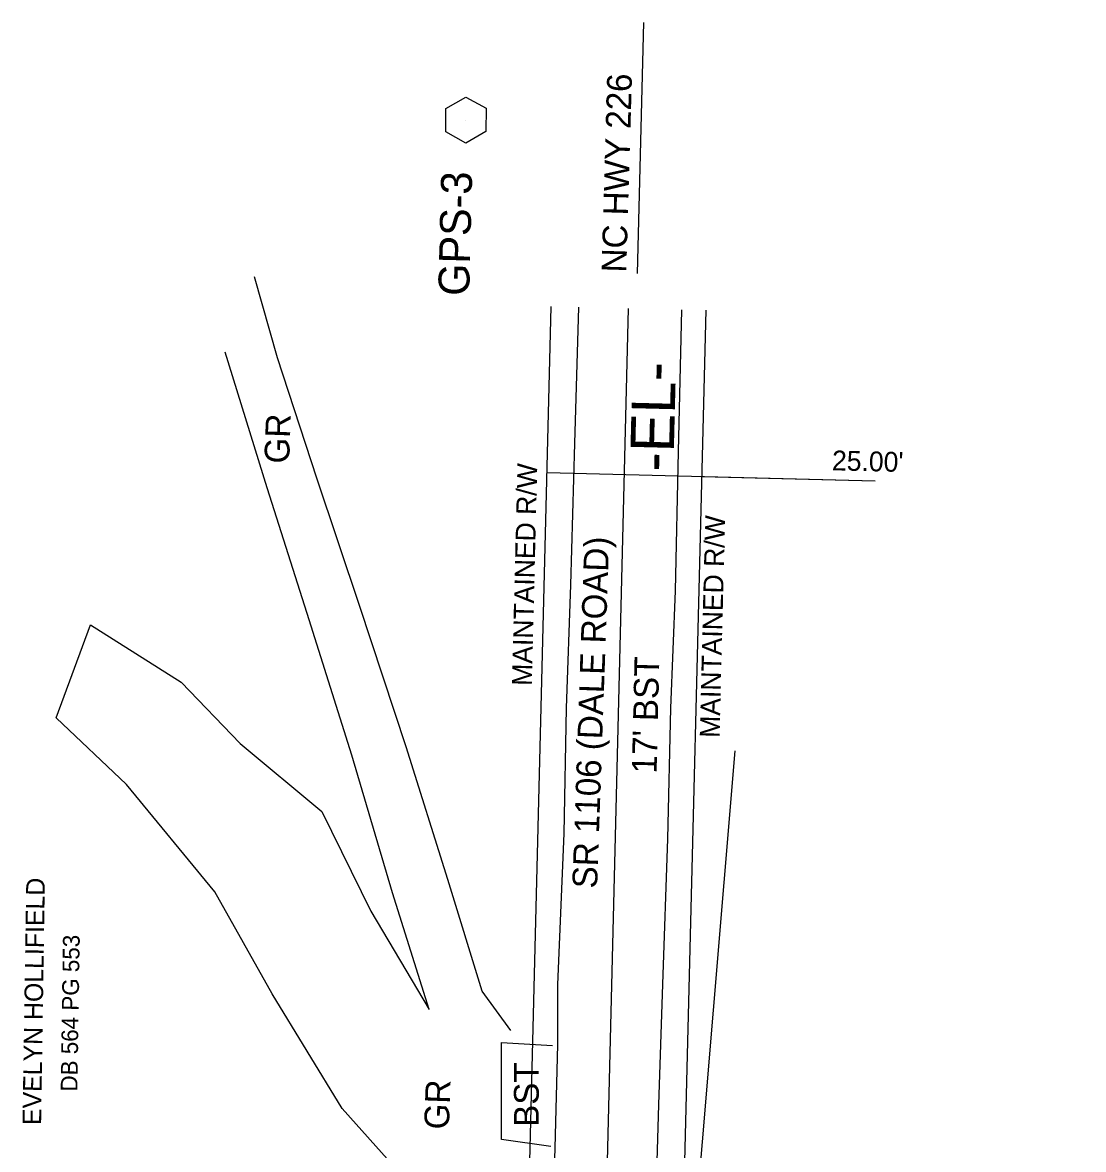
# Model space of a CAD drawing. Extents: x 1088366 to 1089341, y 781245 to 782648.
# Drawn here: x 1088767.2 to 1088938.3, y 781843.2 to 782025 of the extents above; entities that cross this region are included whole.
import ezdxf

# ---------------------------------------------------------------- set-up
doc = ezdxf.new("R2010")
doc.units = 0
for name, color, linetype in [('CTL Primary Horizontal and Vertical CELL', 7, 'Continuous'), ('CTL Primary Horizontal and Vertical Text', 7, 'Continuous'), ('Exist Horizontal Alignment', 7, 'Continuous'), ('Exist Horizontal Alignment Direction Label', 7, 'Continuous'), ('Exist Property Deed Book Text', 7, 'Continuous'), ('Exist Property Owner Text', 7, 'Continuous'), ('Exist Right of Way Line', 7, 'Continuous'), ('Exist Right of Way Line Text', 7, 'Continuous'), ('Exist Right of Way Width CELL', 7, 'Continuous'), ('Exist Roads EOP', 7, 'Continuous'), ('Exist Roads EOP Leader', 7, 'Continuous'), ('Exist Roads EOP Text', 7, 'Continuous'), ('Exist Roads Soil', 7, 'Continuous'), ('Exist Roads Soil Text', 7, 'Continuous'), ('Exist Vegetation Woods Line', 7, 'Continuous')]:
    doc.layers.add(name, color=color, linetype=linetype)

msp = doc.modelspace()

# ---------------------------------------------------------------- linework, layer by layer
at = {"layer": 'CTL Primary Horizontal and Vertical CELL'}
msp.add_line((1088838.71, 782009.27), (1088838.71, 782009.27), dxfattribs=at)
msp.add_lwpolyline([(1088835.48, 782011.14), (1088838.73, 782012.95), (1088841.98, 782011.16), (1088841.93, 782007.44), (1088838.68, 782005.55), (1088835.48, 782007.36)], close=True, dxfattribs=at)
at = {"layer": 'Exist Horizontal Alignment'}
msp.add_line((1088858.13, 781704.91), (1088864.96, 781978.89), dxfattribs=at)
at = {"layer": 'Exist Right of Way Line'}
for p, q in [((1088845.64, 781705.22), (1088852.47, 781979.2)), ((1088870.63, 781704.6), (1088877.46, 781978.58))]:
    msp.add_line(p, q, dxfattribs=at)
at = {"layer": 'Exist Right of Way Width CELL'}
for p in [(1088851.8, 781952.39), (1088876.79, 781951.76)]:
    msp.add_line(p, (1088904.72, 781951.07), dxfattribs=at)
at = {"layer": 'Exist Roads EOP'}
for points in [[(1088856.86, 781979.09), (1088856.22, 781957.08), (1088855.57, 781934.3), (1088854.88, 781914.39), (1088854.52, 781894.14), (1088853.51, 781869.82), (1088853.47, 781860.13), (1088853.06, 781843.4), (1088852.42, 781823.3), (1088852.15, 781809.3), (1088851.65, 781789.26), (1088851.14, 781767.36), (1088850.59, 781747.04), (1088849.91, 781705.29), (1088848.76, 781686.19)], [(1088873.5, 781978.67), (1088872.95, 781955.77), (1088872.48, 781933.34), (1088871.73, 781914.36), (1088871.22, 781893.29), (1088870.41, 781869.88), (1088869.8, 781850.38), (1088869.18, 781830.31), (1088868.84, 781810.65), (1088868.33, 781781.83), (1088867.86, 781767.06), (1088867.68, 781744.62), (1088867.34, 781738.14), (1088866.47, 781715.27), (1088865.39, 781693.19), (1088864.42, 781676.36)], [(1088873.5, 781978.67), (1088872.95, 781955.77), (1088872.48, 781933.34), (1088871.73, 781914.36), (1088871.22, 781893.29), (1088870.41, 781869.88), (1088869.8, 781850.38), (1088869.18, 781830.31), (1088868.84, 781810.65), (1088868.33, 781781.83), (1088867.86, 781767.06), (1088867.68, 781744.62)], [(1088852.42, 781843.65), (1088844.47, 781844.81), (1088844.47, 781860.47), (1088852.68, 781859.99)]]:
    msp.add_lwpolyline(points, dxfattribs=at)
at = {"layer": 'Exist Roads EOP Leader'}
msp.add_line((1088867.36, 782025), (1088866.35, 781984.53), dxfattribs=at)
at = {"layer": 'Exist Roads Soil'}
for points in [[(1088845.94, 781862.39), (1088841.32, 781868.72), (1088835.78, 781886.77), (1088829.08, 781908.16), (1088821.63, 781930.78), (1088814.67, 781951.51), (1088808.34, 781970.9), (1088804.6, 781983.99)], [(1088851.73, 781822.38), (1088840.35, 781825.46), (1088830.55, 781836.64), (1088818.74, 781849.8), (1088807.48, 781868.3), (1088798.2, 781884.76), (1088783.96, 781902.06), (1088772.62, 781912.82), (1088778.19, 781927.81), (1088792.77, 781918.56), (1088802.3, 781908.7), (1088815.5, 781897.74), (1088823.39, 781881.66), (1088832.79, 781865.75), (1088826.9, 781884.58), (1088820.34, 781906.83), (1088813.13, 781929.64), (1088806.68, 781949.91), (1088799.87, 781971.84)]]:
    msp.add_lwpolyline(points, dxfattribs=at)
at = {"layer": 'Exist Vegetation Woods Line'}
msp.add_lwpolyline([(1088938.32, 781707.06), (1088898.21, 781719.36), (1088881.24, 781725.94), (1088868.09, 781739.51), (1088882.14, 781907.48)], dxfattribs=at)

# ---------------------------------------------------------------- texts
at = {"layer": 'CTL Primary Horizontal and Vertical Text'}
msp.add_text('GPS-3', height=5, rotation=88.5723, dxfattribs=at).set_placement((1088839.24, 781980.86))
at = {"layer": 'Exist Horizontal Alignment Direction Label'}
msp.add_text('-EL-', height=7, rotation=88.5723, dxfattribs=at).set_placement((1088872.17, 781952.49))
at = {"layer": 'Exist Property Deed Book Text'}
msp.add_text('DB 564 PG 553', height=2.7, rotation=89.1135, dxfattribs=at).set_placement((1088776.05, 781852.52))
at = {"layer": 'Exist Property Owner Text'}
msp.add_text('EVELYN HOLLIFIELD', height=3, rotation=89.1135, dxfattribs=at).set_placement((1088770.2, 781847.11))
at = {"layer": 'Exist Right of Way Line Text'}
for p in [(1088849.34, 781917.96), (1088879.63, 781909.57)]:
    msp.add_text('MAINTAINED R/W', height=3.2, rotation=88.5723, dxfattribs=at).set_placement(p)
at = {"layer": 'Exist Right of Way Width CELL'}
msp.add_text("25.00'", height=3.2, rotation=358.5723, dxfattribs=at).set_placement((1088897.73, 781952.77))
at = {"layer": 'Exist Roads EOP Text'}
for s, rotation, p in [('NC HWY 226', 88.3321, (1088864.58, 781984.63)), ('SR 1106 (DALE ROAD)', 88.0037, (1088859.87, 781885.26)), ("17' BST", 88.6245, (1088869.47, 781903.81)), ('BST', 89.9854, (1088850.47, 781846.84))]:
    msp.add_text(s, height=4, rotation=rotation, dxfattribs=at).set_placement(p)
at = {"layer": 'Exist Roads Soil Text'}
for p in [(1088810.2, 781953.8), (1088835.97, 781846.37)]:
    msp.add_text('GR', height=4, rotation=88.0036, dxfattribs=at).set_placement(p)

doc.saveas('drawing.dxf')
